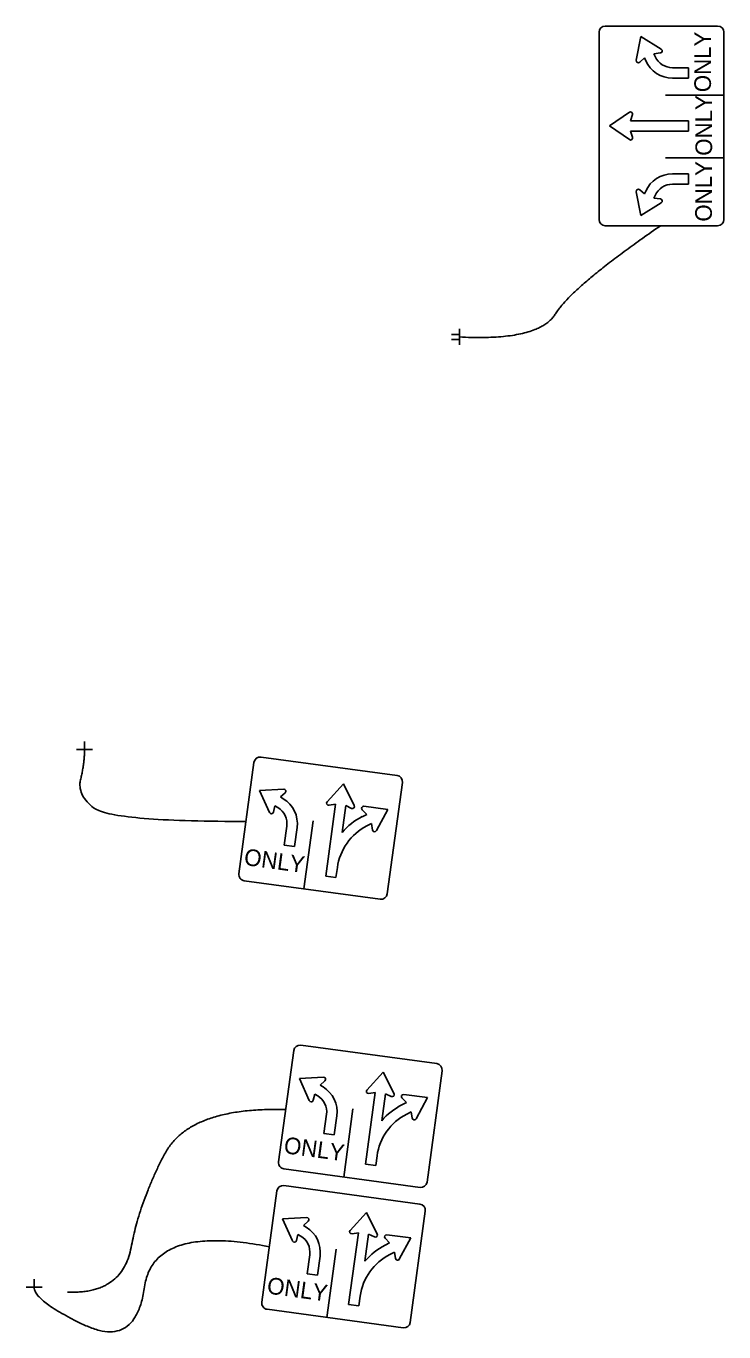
# Model space of a CAD drawing. Extents: x 1817563 to 1822411, y 498049 to 499279.
# Drawn here: x 1817562.7 to 1817702.5, y 499001.8 to 499263.4 of the extents above; entities that cross this region are included whole.
import ezdxf

# ---------------------------------------------------------------- set-up
doc = ezdxf.new("R2010")
doc.units = 0
doc.layers.add('PM_X_Stop_Line', color=7, linetype='Continuous')
doc.layers.add('SC_Scratch2', color=7, linetype='Continuous')

msp = doc.modelspace()

# ---------------------------------------------------------------- linework, layer by layer
at = {"layer": 'PM_X_Stop_Line'}
for p, q in [((1817684.96, 499256.54), (1817685.84, 499261.29)), ((1817685.84, 499261.29), (1817689.96, 499258.76)), ((1817686.61, 499257), (1817685.64, 499256.15)), ((1817686.87, 499256.42), (1817686.61, 499257)), ((1817689.79, 499258), (1817688.51, 499257.85)), ((1817688.51, 499257.85), (1817688.77, 499257.27)), ((1817692.2, 499255.04), (1817695.43, 499255.04)), ((1817695.43, 499255.04), (1817695.43, 499252.96)), ((1817695.43, 499252.96), (1817692.2, 499252.96)), ((1817690.84, 499249.52), (1817702.51, 499249.52)), ((1817679.59, 499243.38), (1817683.58, 499246.11)), ((1817683.58, 499246.11), (1817679.59, 499243.38)), ((1817684.21, 499245.65), (1817683.83, 499244.42)), ((1817683.83, 499244.42), (1817684.21, 499245.65)), ((1817683.83, 499244.42), (1817695.43, 499244.42)), ((1817695.43, 499244.42), (1817683.83, 499244.42)), ((1817695.43, 499244.42), (1817695.43, 499242.33)), ((1817695.43, 499242.33), (1817695.43, 499244.42)), ((1817683.58, 499240.64), (1817679.59, 499243.38)), ((1817679.59, 499243.38), (1817683.58, 499240.64)), ((1817695.43, 499242.33), (1817683.83, 499242.33)), ((1817683.83, 499242.33), (1817684.21, 499241.1)), ((1817684.21, 499241.1), (1817683.83, 499242.33)), ((1817683.83, 499242.33), (1817695.43, 499242.33)), ((1817690.84, 499237.02), (1817702.51, 499237.02)), ((1817695.43, 499233.79), (1817692.2, 499233.79)), ((1817695.43, 499231.71), (1817695.43, 499233.79)), ((1817692.2, 499231.71), (1817695.43, 499231.71)), ((1817684.96, 499230.21), (1817685.84, 499225.46)), ((1817686.61, 499229.75), (1817685.64, 499230.6)), ((1817686.87, 499230.33), (1817686.61, 499229.75)), ((1817688.51, 499228.9), (1817688.77, 499229.48)), ((1817689.79, 499228.76), (1817688.51, 499228.9)), ((1817685.84, 499225.46), (1817689.96, 499227.99)), ((1817649.55, 499202.71), (1817649.55, 499199.51)), ((1817649.55, 499201.59), (1817647.95, 499201.59)), ((1817649.55, 499200.63), (1817647.95, 499200.63)), ((1817649.55, 499201.11), (1817649.55, 499201.11)), ((1817649.55, 499201.11), (1817649.55, 499201.11)), ((1817576.04, 499118.51), (1817572.84, 499118.51)), ((1817574.44, 499118.51), (1817574.44, 499120.11)), ((1817609.51, 499110.28), (1817614.34, 499110.56)), ((1817626.3, 499111.58), (1817623.05, 499108)), ((1817628.47, 499107.26), (1817626.3, 499111.58)), ((1817611.5, 499105.87), (1817609.51, 499110.28)), ((1817614.64, 499109.83), (1817613.67, 499108.98)), ((1817613.67, 499108.98), (1817614.26, 499108.62)), ((1817612.59, 499107.19), (1817612.28, 499105.94)), ((1817613.18, 499106.84), (1817612.59, 499107.19)), ((1817624.69, 499107.52), (1817622.75, 499093.14)), ((1817623.42, 499107.31), (1817624.69, 499107.52)), ((1817626.03, 499101.85), (1817626.76, 499107.24)), ((1817626.76, 499107.24), (1817627.93, 499106.7)), ((1817630.06, 499106.41), (1817630.96, 499105.49)), ((1817630.96, 499105.49), (1817630.06, 499105.03)), ((1817635.2, 499106.48), (1817630.41, 499107.11)), ((1817632.9, 499102.23), (1817635.2, 499106.48)), ((1817614.44, 499099.31), (1817614.95, 499103.13)), ((1817617.02, 499102.85), (1817616.5, 499099.03)), ((1817620.25, 499104.2), (1817618.4, 499090.57)), ((1817631.01, 499103.17), (1817631.9, 499103.63)), ((1817631.9, 499103.63), (1817632.12, 499102.36)), ((1817616.5, 499099.03), (1817614.44, 499099.31)), ((1817624.81, 499092.86), (1817625.08, 499094.82)), ((1817622.75, 499093.14), (1817624.81, 499092.86)), ((1817614.11, 499024.45), (1817618.93, 499024.73)), ((1817616.09, 499020.04), (1817614.11, 499024.45)), ((1817630.89, 499025.75), (1817627.64, 499022.17)), ((1817633.07, 499021.43), (1817630.89, 499025.75)), ((1817619.23, 499024), (1817618.27, 499023.15)), ((1817618.27, 499023.15), (1817618.85, 499022.79)), ((1817629.29, 499021.69), (1817627.34, 499007.31)), ((1817628.02, 499021.48), (1817629.29, 499021.69)), ((1817617.19, 499021.36), (1817616.88, 499020.11)), ((1817617.77, 499021.01), (1817617.19, 499021.36)), ((1817630.62, 499016.02), (1817631.35, 499021.41)), ((1817631.35, 499021.41), (1817632.52, 499020.87)), ((1817634.65, 499020.58), (1817635.55, 499019.66)), ((1817635.55, 499019.66), (1817634.66, 499019.2)), ((1817639.8, 499020.65), (1817635.01, 499021.28)), ((1817637.49, 499016.4), (1817639.8, 499020.65)), ((1817619.03, 499013.48), (1817619.55, 499017.3)), ((1817621.61, 499017.02), (1817621.1, 499013.2)), ((1817624.84, 499018.37), (1817623, 499004.74)), ((1817635.6, 499017.34), (1817636.5, 499017.8)), ((1817636.5, 499017.8), (1817636.71, 499016.53)), ((1817564.34, 499010.81), (1817564.34, 499012.41)), ((1817621.1, 499013.2), (1817619.03, 499013.48)), ((1817565.94, 499010.81), (1817562.74, 499010.81)), ((1817629.4, 499007.03), (1817629.67, 499008.99)), ((1817627.34, 499007.31), (1817629.4, 499007.03))]:
    msp.add_line(p, q, dxfattribs=at)
for points in [[(1817677.51, 499224.63), (1817677.51, 499262.13)], [(1817677.51, 499262.13), (1817677.51, 499224.63)], [(1817678.76, 499263.38), (1817701.26, 499263.38)], [(1817701.26, 499263.38), (1817678.76, 499263.38)], [(1817702.51, 499262.13), (1817702.51, 499224.63)], [(1817702.51, 499224.63), (1817702.51, 499262.13)], [(1817701.26, 499223.38), (1817678.76, 499223.38)], [(1817678.76, 499223.38), (1817701.26, 499223.38)], [(1817608.38, 499115.9), (1817605.36, 499093.6)], [(1817637.04, 499113.27), (1817609.79, 499116.97)], [(1817635.09, 499089.57), (1817638.11, 499111.87)], [(1817606.43, 499092.19), (1817633.68, 499088.5)], [(1817612.97, 499030.07), (1817609.95, 499007.77)], [(1817641.63, 499027.44), (1817614.38, 499031.14)], [(1817639.68, 499003.74), (1817642.7, 499026.04)], [(1817611.02, 499006.36), (1817638.28, 499002.67)]]:
    msp.add_lwpolyline(points, dxfattribs=at)
for centre, radius, start, end in [((1817678.76, 499262.13), 1.25, 90, 180), ((1817678.76, 499262.13), 1.25, 90, 180), ((1817701.26, 499262.13), 1.25, 360, 90), ((1817701.26, 499262.13), 1.25, 0, 90), ((1817692.2, 499258.79), 3.75, 203.8986, 270), ((1817689.75, 499258.41), 0.417, 276.5948, 58.4729), ((1817685.37, 499256.46), 0.417, 169.4403, 311.3184), ((1817692.2, 499258.79), 5.83, 203.9101, 270), ((1817683.81, 499245.77), 0.417, 342.6382, 124.5163), ((1817683.81, 499245.77), 0.417, 342.6382, 124.5163), ((1817683.81, 499240.98), 0.417, 235.4837, 17.3618), ((1817683.81, 499240.98), 0.417, 235.4837, 17.3618), ((1817692.2, 499227.96), 5.83, 90, 156.0899), ((1817685.37, 499230.29), 0.417, 48.6816, 190.5597), ((1817692.2, 499227.96), 3.75, 90, 156.1014), ((1817689.75, 499228.34), 0.417, 301.5271, 83.4052), ((1817678.76, 499224.63), 1.25, 180, 270), ((1817678.76, 499224.63), 1.25, 180, 270), ((1817701.26, 499224.63), 1.25, 270, 360), ((1817701.26, 499224.63), 1.25, 270, 0), ((1817609.62, 499115.73), 1.25, 82.2841, 172.2841), ((1817636.87, 499112.04), 1.25, 352.2841, 82.2841), ((1817614.36, 499110.14), 0.417, 311.4563, 93.3344), ((1817611.24, 499103.63), 5.83, 352.2841, 58.8182), ((1817623.35, 499107.72), 0.417, 137.7678, 279.646), ((1817611.88, 499106.04), 0.417, 204.3018, 346.18), ((1817611.24, 499103.63), 3.75, 352.2841, 58.8182), ((1817628.1, 499107.07), 0.417, 244.9223, 26.8004), ((1817630.36, 499106.7), 0.417, 82.4699, 224.3481), ((1817636.02, 499093.34), 11.04, 116.9863, 172.2841), ((1817636.02, 499093.34), 13.13, 116.9863, 139.5586), ((1817632.53, 499102.43), 0.417, 189.6244, 331.5025), ((1817606.6, 499093.43), 1.25, 172.2841, 262.2841), ((1817633.85, 499089.74), 1.25, 262.2841, 352.2841), ((1817614.21, 499029.9), 1.25, 82.2841, 172.2841), ((1817641.46, 499026.21), 1.25, 352.2841, 82.2841), ((1817618.96, 499024.31), 0.417, 311.4563, 93.3344), ((1817615.83, 499017.8), 5.83, 352.2841, 58.8182), ((1817627.95, 499021.89), 0.417, 137.7678, 279.646), ((1817632.7, 499021.24), 0.417, 244.9223, 26.8004), ((1817616.47, 499020.21), 0.417, 204.3018, 346.18), ((1817615.83, 499017.8), 3.75, 352.2841, 58.8182), ((1817640.61, 499007.5), 13.13, 116.9863, 139.5586), ((1817634.95, 499020.87), 0.417, 82.4699, 224.3481), ((1817640.61, 499007.5), 11.04, 116.9863, 172.2841), ((1817637.13, 499016.6), 0.417, 189.6244, 331.5025), ((1817611.19, 499007.6), 1.25, 172.2841, 262.2841), ((1817638.44, 499003.91), 1.25, 262.2841, 352.2841)]:
    msp.add_arc(centre, radius, start, end, dxfattribs=at)
for points in [[(1817689.8, 499223.38), (1817672.17, 499211.23), (1817665.4, 499200.27), (1817649.55, 499201.11)], [(1817574.44, 499118.51), (1817574.44, 499115.66), (1817572.88, 499109.39), (1817579.82, 499104.1), (1817606.77, 499104.04)], [(1817564.34, 499010.81), (1817564.34, 499007.96), (1817584.71, 498998.38), (1817588.25, 499023.43), (1817611.46, 499018.89)]]:
    msp.add_open_spline(points, degree=2, dxfattribs=at)
at = {"layer": 'SC_Scratch2'}
for p, q in [((1817617.48, 499052.56), (1817622.3, 499052.84)), ((1817634.26, 499053.86), (1817631.01, 499050.28)), ((1817636.44, 499049.54), (1817634.26, 499053.86)), ((1817619.46, 499048.15), (1817617.48, 499052.56)), ((1817622.6, 499052.11), (1817621.64, 499051.26)), ((1817621.64, 499051.26), (1817622.22, 499050.9)), ((1817620.56, 499049.48), (1817620.25, 499048.22)), ((1817621.14, 499049.12), (1817620.56, 499049.48)), ((1817632.66, 499049.8), (1817630.71, 499035.42)), ((1817631.39, 499049.59), (1817632.66, 499049.8)), ((1817633.99, 499044.13), (1817634.72, 499049.52)), ((1817634.72, 499049.52), (1817635.89, 499048.98)), ((1817638.02, 499048.69), (1817638.92, 499047.77)), ((1817638.92, 499047.77), (1817638.03, 499047.31)), ((1817643.17, 499048.76), (1817638.38, 499049.39)), ((1817640.86, 499044.51), (1817643.17, 499048.76)), ((1817622.4, 499041.59), (1817622.92, 499045.41)), ((1817624.98, 499045.13), (1817624.47, 499041.31)), ((1817628.21, 499046.48), (1817626.37, 499032.85)), ((1817638.97, 499045.46), (1817639.87, 499045.91)), ((1817639.87, 499045.91), (1817640.08, 499044.64)), ((1817624.47, 499041.31), (1817622.4, 499041.59)), ((1817630.71, 499035.42), (1817632.78, 499035.14)), ((1817632.78, 499035.14), (1817633.04, 499037.1))]:
    msp.add_line(p, q, dxfattribs=at)
for points in [[(1817616.34, 499058.18), (1817613.32, 499035.88)], [(1817645, 499055.56), (1817617.75, 499059.25)], [(1817643.05, 499031.85), (1817646.07, 499054.15)], [(1817614.39, 499034.47), (1817641.65, 499030.78)]]:
    msp.add_lwpolyline(points, dxfattribs=at)
for centre, radius, start, end in [((1817617.58, 499058.01), 1.25, 82.2841, 172.2841), ((1817644.83, 499054.32), 1.25, 352.2841, 82.2841), ((1817622.33, 499052.42), 0.417, 311.4563, 93.3344), ((1817619.2, 499045.91), 5.83, 352.2841, 58.8182), ((1817631.32, 499050), 0.417, 137.7678, 279.646), ((1817619.84, 499048.32), 0.417, 204.3018, 346.18), ((1817619.2, 499045.91), 3.75, 352.2841, 58.8182), ((1817636.07, 499049.36), 0.417, 244.9223, 26.8004), ((1817638.32, 499048.98), 0.417, 82.4699, 224.3481), ((1817643.98, 499035.62), 11.04, 116.9863, 172.2841), ((1817643.98, 499035.62), 13.13, 116.9863, 139.5586), ((1817640.5, 499044.71), 0.417, 189.6244, 331.5025), ((1817614.56, 499035.71), 1.25, 172.2841, 262.2841), ((1817641.81, 499032.02), 1.25, 262.2841, 352.2841)]:
    msp.add_arc(centre, radius, start, end, dxfattribs=at)
msp.add_open_spline([(1817614.75, 499046.37), (1817595.49, 499046.88), (1817585.54, 499028.12), (1817581.98, 499009.34), (1817571.03, 499009.8)], degree=2, dxfattribs=at)

# ---------------------------------------------------------------- texts
at = {"layer": 'PM_X_Stop_Line'}
for rotation, p in [(90, (1817699.92, 499250.14)), (90, (1817700.15, 499237.41)), (90, (1817700.1, 499224.21)), (352.2841, (1817606.25, 499095.37)), (352.2841, (1817610.85, 499009.54))]:
    msp.add_text('ONLY', height=3.333, rotation=rotation, dxfattribs=at).set_placement(p)
at = {"layer": 'SC_Scratch2'}
msp.add_text('ONLY', height=3.333, rotation=352.2841, dxfattribs=at).set_placement((1817614.22, 499037.65))

doc.saveas('drawing.dxf')
